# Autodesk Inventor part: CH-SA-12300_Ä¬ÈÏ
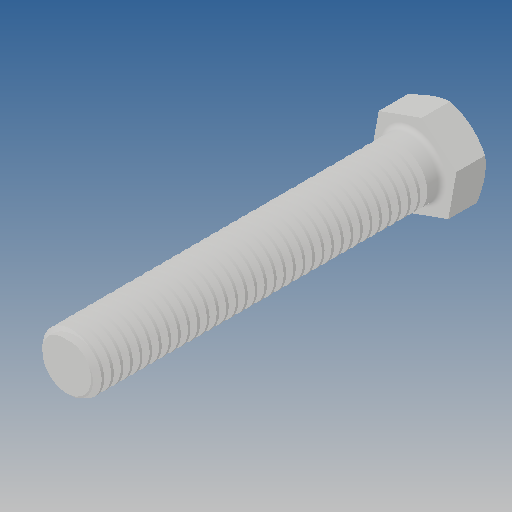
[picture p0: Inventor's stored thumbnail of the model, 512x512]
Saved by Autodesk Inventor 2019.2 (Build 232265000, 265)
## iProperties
Created: 2010-06
Part Number: CH-SA-12300_Ä¬ÈÏ
Material: Ogólny
Document SubType Name: Modeling
Designer: CADENGINEERING4
Density: 1 g/cm^3
Appearance: Domyślna
Author: CADENGINEERING4
Revision Number: ÈÎºÎ
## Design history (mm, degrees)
feature "NONE"
node "Bryła1"
